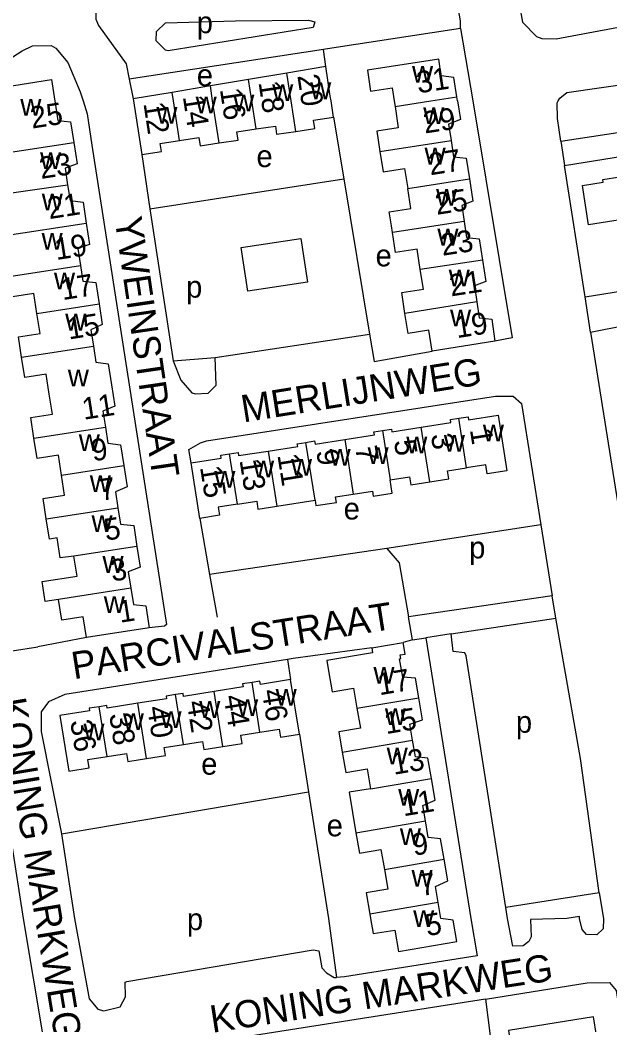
# Model space of a CAD drawing. Extents: x 159675 to 162108, y 386471 to 388472.
# Drawn here: x 160527.6 to 160635.8, y 387080.5 to 387264.8 of the extents above; entities that cross this region are included whole.
import ezdxf

# ---------------------------------------------------------------- set-up
doc = ezdxf.new("R2010")
doc.units = 0
for name, color, linetype in [('BLT_Basislijn', 7, 'Continuous'), ('BLT_Bebouwing', 7, 'Continuous'), ('BLT_Centroide', 7, 'Continuous'), ('BLT_Huisnummer', 7, 'Continuous'), ('BLT_Huisnummer_ tussenligend', 7, 'Continuous'), ('BLT_Onderverdeling_panden', 7, 'Continuous'), ('BLT_Straatnaam', 7, 'Continuous')]:
    doc.layers.add(name, color=color, linetype=linetype)

msp = doc.modelspace()

# ---------------------------------------------------------------- linework, layer by layer
at = {"layer": 'BLT_Basislijn'}
for p, q in [((160608.39, 387263.31), (160610.61, 387250)), ((160583.24, 387259.43), (160547.57, 387254.03)), ((160583.66, 387256.31), (160583.24, 387259.43)), ((160547.57, 387254.03), (160548.32, 387250.37)), ((160585.06, 387247.02), (160586.93, 387235.71)), ((160627.45, 387238.19), (160689.22, 387248.08)), ((160626.76, 387242.65), (160627.45, 387238.19)), ((160549.87, 387240.15), (160551.38, 387230.21)), ((160551.38, 387230.21), (160586.93, 387235.71)), ((160586.93, 387235.71), (160591.67, 387207.2)), ((160551.38, 387230.21), (160555.63, 387202.32)), ((160631.23, 387214.07), (160671.48, 387220.54)), ((160632.21, 387207.58), (160631.23, 387214.07)), ((160632.21, 387207.58), (160639.03, 387208.93)), ((160563.34, 387202.93), (160591.67, 387207.2)), ((160555.63, 387202.32), (160563.34, 387202.93)), ((160560.54, 387173.4), (160562.32, 387163.13)), ((160623.13, 387172.21), (160594.84, 387167.88)), ((160623.13, 387172.21), (160625.17, 387159.18)), ((160594.84, 387167.88), (160562.32, 387163.13)), ((160562.32, 387163.13), (160563.69, 387155.25)), ((160625.17, 387159.18), (160598.8, 387155.31)), ((160625.83, 387155.07), (160625.17, 387159.18)), ((160599.55, 387151.11), (160598.8, 387155.31)), ((160606.67, 387152.23), (160625.83, 387155.07)), ((160630.38, 387129.33), (160625.83, 387155.07)), ((160539.73, 387151.54), (160530.8, 387149.82)), ((160599.55, 387151.11), (160597.84, 387150.61)), ((160599.55, 387151.11), (160602.02, 387151.49)), ((160606.67, 387152.23), (160602.02, 387151.49)), ((160526.11, 387149.08), (160530.8, 387149.82)), ((160576.6, 387147.54), (160577.19, 387143.83)), ((160578.8, 387133.78), (160580.48, 387123.24)), ((160633.79, 387104.72), (160630.38, 387129.33)), ((160535.15, 387115.53), (160580.48, 387123.24)), ((160633.79, 387104.72), (160616.66, 387102))]:
    msp.add_line(p, q, dxfattribs=at)
for points in [[(160608.39, 387263.31), (160608.39, 387264.71), (160606.91, 387273.02), (160605.41, 387274.93), (160594.73, 387274.96), (160594.31, 387274.52), (160594.06, 387269.42), (160593.75, 387269.01), (160557.12, 387269.57), (160556.66, 387273.85), (160555.19, 387274.98), (160545.49, 387273.39), (160543.1, 387271.61), (160541.45, 387268.66), (160541.45, 387265), (160541.92, 387263.87), (160547, 387256.8), (160547.57, 387254.03)], [(160618.08, 387273.69), (160619.73, 387264.46), (160622.28, 387261.82), (160623.3, 387261.46), (160625.94, 387261.42), (160643.22, 387264.62), (160645.03, 387266.59)], [(160567.06, 387264.7), (160580.48, 387264.84), (160581.65, 387264.55), (160581.32, 387263.47), (160554.72, 387259.2), (160554.24, 387259.3), (160552.53, 387261.02), (160552.58, 387262.77), (160554.27, 387264.36), (160567.06, 387264.7)], [(160608.39, 387263.31), (160583.95, 387259.54), (160583.24, 387259.43)], [(160513.63, 387250), (160527.93, 387259.23), (160529.83, 387260.15), (160533.25, 387260.2), (160534.14, 387259.72), (160536.35, 387257.05), (160538.58, 387251.67), (160539.11, 387250)], [(160626.28, 387250), (160626.58, 387250.54), (160627.89, 387251.53), (160647.35, 387254.35)], [(160539.11, 387250), (160539.86, 387247.66), (160540.75, 387241.89)], [(160610.61, 387250), (160617.86, 387206.53), (160614.67, 387205.95)], [(160626.76, 387242.65), (160626.13, 387246.76), (160626.1, 387249.66), (160626.28, 387250)], [(160626.76, 387242.65), (160655.7, 387247.02), (160655.92, 387247.72), (160652.97, 387250)], [(160540.75, 387241.89), (160554.4, 387153.93), (160554.08, 387153.61), (160551.26, 387153.35)], [(160631.23, 387214.07), (160631.17, 387214.43), (160627.45, 387238.19)], [(160591.67, 387207.2), (160592.5, 387202.18), (160603.14, 387204.11)], [(160632.21, 387207.58), (160649.34, 387100), (160649.87, 387098.07)], [(160555.63, 387202.32), (160557.07, 387198.77), (160559.05, 387196.47), (160559.68, 387196.26), (160562.05, 387196.38), (160563.56, 387197.85), (160563.34, 387202.93)], [(160558.92, 387183.59), (160558.52, 387186.03), (160560.69, 387187.29), (160561.76, 387187.66), (160614.79, 387195.84), (160618.03, 387195.84), (160619.58, 387194.51), (160623.13, 387172.21)], [(160594.84, 387167.88), (160597.14, 387165.23), (160598.8, 387155.31)], [(160602.02, 387151.49), (160610.25, 387100), (160611.42, 387093.14), (160587.1, 387089.27), (160585.62, 387089.18)], [(160616.66, 387102), (160609.39, 387148.21), (160609.18, 387148.71), (160607.04, 387148.97), (160606.67, 387152.23)], [(160592.07, 387149.63), (160577.65, 387147.7), (160576.6, 387147.54)], [(160576.6, 387147.54), (160535.78, 387141.1), (160532.76, 387139.74), (160531.45, 387137.88), (160531.42, 387134.27), (160535.15, 387115.53)], [(160580.48, 387123.24), (160584.17, 387100), (160585.62, 387089.18)], [(160525.82, 387114.65), (160525.96, 387113.82), (160528.15, 387100), (160531.84, 387077.71)], [(160535.15, 387115.53), (160537.56, 387100), (160540.24, 387085.27), (160541.84, 387083.36), (160542.95, 387083.03), (160545.92, 387083.78), (160546.88, 387085.59), (160546.82, 387088.32), (160547.17, 387088.44), (160581.36, 387094.22), (160582.38, 387094.03), (160582.92, 387090.91), (160583.78, 387090.02), (160585.21, 387089.16), (160585.62, 387089.18)], [(160633.79, 387104.72), (160634.59, 387100), (160634.55, 387098.11), (160633.4, 387096.96), (160631.48, 387097.04), (160630.69, 387097.98), (160630.21, 387100), (160630.17, 387100.37), (160627.87, 387100), (160621.18, 387099.79), (160621.35, 387096.6), (160620.87, 387095.76), (160619.86, 387094.95), (160617.98, 387094.89), (160616.96, 387100), (160616.66, 387102)], [(160612.92, 387085.16), (160631.58, 387088.2), (160635.7, 387088.25), (160636.9, 387086.77), (160641.18, 387058.71)], [(160612.92, 387085.16), (160539.47, 387073.63), (160538.99, 387073.76), (160537.63, 387074.35)], [(160612.92, 387085.16), (160613.78, 387078.48), (160616.69, 387061.42)]]:
    msp.add_lwpolyline(points, dxfattribs=at)
msp.add_lwpolyline([(160568.1, 387223.09), (160579.06, 387224.78), (160580.3, 387216.78), (160569.34, 387215.09)], close=True, dxfattribs=at)
at = {"layer": 'BLT_Bebouwing'}
for p, q in [((160583.66, 387256.31), (160576.52, 387255.11)), ((160576.52, 387255.11), (160569.49, 387253.93)), ((160562.48, 387252.75), (160555.46, 387251.57)), ((160569.49, 387253.93), (160562.48, 387252.75)), ((160555.46, 387251.57), (160548.32, 387250.37)), ((160548.32, 387250.37), (160548.38, 387250)), ((160607.83, 387250), (160607.71, 387250.74)), ((160548.38, 387250), (160549.87, 387240.15)), ((160585.06, 387247.02), (160584.62, 387250)), ((160596.19, 387250), (160596.35, 387248.98)), ((160614.67, 387205.95), (160603.14, 387204.11)), ((160560.54, 387173.4), (160558.92, 387183.59)), ((160574.65, 387175.64), (160581.67, 387176.75)), ((160551.26, 387153.35), (160539.73, 387151.54)), ((160592.07, 387149.63), (160597.84, 387150.61)), ((160578.8, 387133.78), (160577.19, 387143.83))]:
    msp.add_line(p, q, dxfattribs=at)
for points in [[(160584.62, 387250), (160584.48, 387250.9), (160583.66, 387256.31)], [(160607.71, 387250.74), (160607.17, 387254.33), (160604.83, 387254.59), (160604.36, 387257.68), (160591.27, 387255.68), (160591.86, 387251.82), (160595.81, 387252.43), (160596.19, 387250)], [(160521.8, 387239.99), (160520.14, 387250.6), (160522.32, 387250.94), (160522.13, 387252.19), (160533.3, 387253.94)], [(160533.3, 387253.94), (160534.48, 387246.4), (160536.81, 387246.19), (160537.41, 387242.37)], [(160596.35, 387248.98), (160596.95, 387245.08), (160593, 387244.47), (160593.58, 387240.73)], [(160607.83, 387250), (160608.35, 387246.59), (160606.19, 387245.75), (160606.65, 387242.76)], [(160578.13, 387244.43), (160581.63, 387244.96), (160581.41, 387246.46), (160585.06, 387247.02)], [(160564.06, 387242.3), (160567.55, 387242.83), (160567.32, 387244.33), (160570.86, 387244.86)], [(160570.86, 387244.86), (160574.4, 387245.4), (160574.63, 387243.9), (160578.13, 387244.43)], [(160556.8, 387242.74), (160560.34, 387243.27), (160560.57, 387241.77), (160564.06, 387242.3)], [(160537.41, 387242.37), (160538.02, 387238.47), (160535.82, 387237.67), (160536.29, 387234.62)], [(160549.87, 387240.15), (160553.49, 387240.7), (160553.26, 387242.2), (160556.8, 387242.74)], [(160606.65, 387242.76), (160607.1, 387239.77), (160609.42, 387239.51), (160610.01, 387235.69)], [(160593.58, 387240.73), (160594.16, 387237), (160598.11, 387237.61), (160598.68, 387233.93)], [(160610.01, 387235.69), (160610.62, 387231.64), (160608.58, 387230.85), (160609.03, 387227.9)], [(160641.94, 387228.84), (160631.85, 387227.28), (160630.74, 387234.49), (160634.56, 387235.09), (160634.48, 387235.61), (160640.74, 387236.58)], [(160536.29, 387234.62), (160536.74, 387231.75), (160539.11, 387231.45), (160539.71, 387227.57)], [(160595.88, 387225.89), (160595.69, 387227.11), (160595.3, 387229.64), (160599.25, 387230.26), (160598.68, 387233.93)], [(160539.71, 387227.57), (160540.32, 387223.67), (160538.16, 387222.91), (160538.64, 387219.82)], [(160609.03, 387227.9), (160609.48, 387224.95), (160611.79, 387224.7), (160612.39, 387220.8)], [(160600.99, 387219.06), (160600.41, 387222.79), (160596.45, 387222.17), (160595.88, 387225.89)], [(160538.64, 387219.82), (160539.09, 387216.96), (160541.43, 387216.68), (160542.04, 387212.75)], [(160598.18, 387211.02), (160597.59, 387214.83), (160601.55, 387215.44), (160600.99, 387219.06)], [(160612.39, 387220.8), (160612.98, 387216.9), (160610.92, 387216.05), (160611.37, 387213.13)], [(160530.66, 387211.01), (160530.1, 387214.69), (160526.15, 387214.09), (160525.58, 387217.82)], [(160542.04, 387212.75), (160542.63, 387208.98), (160540.53, 387208.01), (160541, 387205)], [(160611.37, 387213.13), (160611.81, 387210.21), (160614.14, 387209.94), (160614.67, 387205.95)], [(160527.84, 387202.99), (160527.27, 387206.73), (160531.22, 387207.34), (160530.66, 387211.01)], [(160603.14, 387204.11), (160602.53, 387207.93), (160598.75, 387207.34), (160598.18, 387211.02)], [(160541, 387205), (160541.45, 387202.1), (160543.73, 387201.75), (160544.33, 387197.92)], [(160532.92, 387196.17), (160532.36, 387199.85), (160528.41, 387199.25), (160527.84, 387202.99)], [(160544.33, 387197.92), (160544.94, 387194), (160542.77, 387193.1), (160543.23, 387190.15)], [(160530.1, 387188.15), (160529.53, 387191.89), (160533.48, 387192.5), (160532.92, 387196.17)], [(160601.14, 387190.13), (160606.6, 387190.99), (160606.51, 387191.54), (160608.05, 387191.78)], [(160608.05, 387191.78), (160609.74, 387192.04), (160609.83, 387191.47), (160615.28, 387192.32), (160616.87, 387182.13), (160613.28, 387181.57), (160613.02, 387183.25), (160609.49, 387182.69)], [(160543.23, 387190.15), (160543.69, 387187.19), (160546.01, 387186.89), (160546.61, 387183.08)], [(160587.12, 387187.86), (160592.57, 387188.71), (160592.48, 387189.28), (160594.08, 387189.53)], [(160594.08, 387189.53), (160595.69, 387189.78), (160595.77, 387189.29), (160601.14, 387190.13)], [(160535.18, 387181.34), (160534.62, 387185.01), (160530.67, 387184.41), (160530.1, 387188.15)], [(160580.01, 387187.36), (160581.58, 387187.61), (160581.67, 387187.01), (160587.12, 387187.86)], [(160573.06, 387185.77), (160578.49, 387186.62), (160578.41, 387187.11), (160580.01, 387187.36)], [(160558.92, 387183.59), (160564.46, 387184.46), (160564.37, 387184.99), (160565.98, 387185.24)], [(160565.98, 387185.24), (160567.55, 387185.49), (160567.64, 387184.92), (160573.06, 387185.77)], [(160546.61, 387183.08), (160547.21, 387179.2), (160545.04, 387178.3), (160545.5, 387175.33)], [(160602.73, 387180.09), (160606.21, 387180.64), (160605.97, 387182.14), (160609.49, 387182.69)], [(160532.36, 387173.33), (160531.79, 387177.07), (160535.74, 387177.67), (160535.18, 387181.34)], [(160588.68, 387177.86), (160592.21, 387178.42), (160592.35, 387177.51), (160595.81, 387178.06), (160595.44, 387180.46)], [(160595.44, 387180.46), (160599.02, 387181.03), (160599.26, 387179.54), (160602.73, 387180.09)], [(160567.44, 387176.03), (160570.97, 387176.59), (160571.21, 387175.09), (160574.65, 387175.64)], [(160581.67, 387176.75), (160581.83, 387175.75), (160585.59, 387176.33), (160585.43, 387177.35), (160588.68, 387177.86)], [(160545.5, 387175.33), (160545.97, 387172.35), (160548.4, 387172.1), (160549, 387168.27)], [(160567.44, 387176.03), (160563.92, 387175.47), (160564.15, 387173.98), (160560.54, 387173.4)], [(160537.45, 387166.46), (160534.92, 387166.15), (160534.36, 387169.81), (160532.93, 387169.59), (160532.36, 387173.33)], [(160549, 387168.27), (160549.6, 387164.44), (160547.4, 387163.57), (160547.87, 387160.59)], [(160534.62, 387158.52), (160532.18, 387158.13), (160531.61, 387161.84), (160538.01, 387162.82), (160537.45, 387166.46)], [(160547.87, 387160.59), (160548.34, 387157.61), (160550.63, 387157.38), (160551.26, 387153.35)], [(160539.73, 387151.54), (160539.13, 387155.35), (160535.19, 387154.75), (160534.62, 387158.52)], [(160592.07, 387149.63), (160592.22, 387148.73), (160583.82, 387147.3), (160584.14, 387145.43), (160584.8, 387141.57), (160588.74, 387142.24), (160589.36, 387138.57)], [(160600.69, 387140.5), (160600.08, 387144.1), (160597.78, 387144.26), (160597.2, 387147.64), (160597.41, 387147.68), (160597.3, 387148.34), (160598.2, 387148.49), (160597.84, 387150.61)], [(160577.19, 387143.83), (160571.64, 387142.94), (160571.54, 387143.55), (160570.11, 387143.32)], [(160563.17, 387141.64), (160557.55, 387140.74), (160557.46, 387141.28), (160556.06, 387141.06)], [(160570.11, 387143.32), (160568.39, 387143.05), (160568.48, 387142.49), (160563.17, 387141.64)], [(160556.06, 387141.06), (160554.35, 387140.79), (160554.42, 387140.32), (160549.15, 387139.47)], [(160599.56, 387132.7), (160599.06, 387135.64), (160601.38, 387136.46), (160600.69, 387140.5)], [(160542.08, 387138.84), (160540.23, 387138.55), (160540.31, 387138.09), (160534.86, 387137.22), (160536.49, 387127.04), (160540.25, 387127.64), (160540.01, 387129.14), (160543.53, 387129.7)], [(160549.15, 387139.47), (160543.53, 387138.58), (160543.45, 387139.07), (160542.08, 387138.84)], [(160589.36, 387138.57), (160589.99, 387134.91), (160586.04, 387134.24), (160586.68, 387130.51)], [(160564.78, 387131.55), (160568.28, 387132.11), (160568.04, 387133.61), (160571.57, 387134.17)], [(160571.57, 387134.17), (160575.09, 387134.73), (160575.33, 387133.23), (160578.8, 387133.78)], [(160557.52, 387131.93), (160561.05, 387132.49), (160561.29, 387130.99), (160564.78, 387131.55)], [(160603.02, 387125.68), (160602.39, 387129.41), (160600.08, 387129.65), (160599.56, 387132.7)], [(160550.76, 387129.32), (160554.23, 387129.88), (160553.99, 387131.37), (160557.52, 387131.93)], [(160586.68, 387130.51), (160587.31, 387126.78), (160591.25, 387127.46), (160591.88, 387123.79)], [(160543.53, 387129.7), (160547.06, 387130.26), (160547.3, 387128.77), (160550.76, 387129.32)], [(160601.92, 387117.89), (160601.45, 387120.71), (160603.7, 387121.68), (160603.02, 387125.68)], [(160591.88, 387123.79), (160587.92, 387123.18), (160588.56, 387119.45), (160589.19, 387115.72)], [(160605.34, 387110.87), (160604.71, 387114.58), (160602.43, 387114.87), (160601.92, 387117.89)], [(160589.19, 387115.72), (160589.83, 387111.99), (160593.77, 387112.67), (160594.39, 387109)], [(160604.29, 387102.92), (160603.79, 387105.88), (160606.01, 387106.88), (160605.34, 387110.87)], [(160594.39, 387109), (160595.02, 387105.34), (160591.07, 387104.67), (160591.73, 387100.8)], [(160591.73, 387100.8), (160591.87, 387100), (160592.34, 387097.2), (160596.29, 387097.87), (160596.96, 387093.93), (160607.68, 387095.75), (160607.01, 387099.7), (160604.78, 387100), (160604.29, 387102.92)], [(160632.76, 387081.95), (160617.16, 387079.46), (160617.79, 387075.55), (160616.9, 387075.41), (160617.04, 387074.56), (160617.9, 387074.69), (160618.7, 387069.68), (160617.3, 387069.46), (160618.68, 387060.87), (160627.39, 387062.26), (160627.19, 387063.5), (160635.49, 387064.83), (160632.76, 387081.95)]]:
    msp.add_lwpolyline(points, dxfattribs=at)
at = {"layer": 'BLT_Onderverdeling_panden'}
for p, q in [((160577.29, 387250), (160576.52, 387255.11)), ((160562.89, 387250), (160562.48, 387252.75)), ((160570.09, 387250), (160569.49, 387253.93)), ((160555.7, 387250), (160555.46, 387251.57)), ((160602.93, 387250), (160607.71, 387250.74)), ((160556.8, 387242.74), (160555.7, 387250)), ((160564.06, 387242.3), (160562.89, 387250)), ((160570.86, 387244.86), (160570.09, 387250)), ((160578.13, 387244.43), (160577.29, 387250)), ((160596.35, 387248.98), (160602.93, 387250)), ((160521.8, 387239.99), (160537.41, 387242.37)), ((160593.58, 387240.73), (160606.65, 387242.76)), ((160598.68, 387233.93), (160610.01, 387235.69)), ((160518.72, 387232.15), (160536.29, 387234.62)), ((160524.45, 387225.23), (160539.71, 387227.57)), ((160609.03, 387227.9), (160595.88, 387225.89)), ((160525.58, 387217.82), (160538.64, 387219.82)), ((160612.39, 387220.8), (160600.99, 387219.06)), ((160530.66, 387211.01), (160542.04, 387212.75)), ((160611.37, 387213.13), (160598.18, 387211.02)), ((160527.84, 387202.99), (160541, 387205)), ((160609.49, 387182.69), (160608.05, 387191.78)), ((160530.1, 387188.15), (160543.23, 387190.15)), ((160594.08, 387189.53), (160595.44, 387180.46)), ((160602.73, 387180.09), (160601.14, 387190.13)), ((160587.12, 387187.86), (160588.68, 387177.86)), ((160581.67, 387176.75), (160580.01, 387187.36)), ((160567.44, 387176.03), (160565.98, 387185.24)), ((160573.06, 387185.77), (160574.65, 387175.64)), ((160535.18, 387181.34), (160546.61, 387183.08)), ((160532.36, 387173.33), (160545.5, 387175.33)), ((160549, 387168.27), (160537.45, 387166.46)), ((160547.87, 387160.59), (160534.62, 387158.52)), ((160564.78, 387131.55), (160563.17, 387141.64)), ((160571.57, 387134.17), (160570.11, 387143.32)), ((160557.52, 387131.93), (160556.06, 387141.06)), ((160589.36, 387138.57), (160600.69, 387140.5)), ((160543.53, 387129.7), (160542.08, 387138.84)), ((160550.76, 387129.32), (160549.15, 387139.47)), ((160586.68, 387130.51), (160599.56, 387132.7)), ((160591.88, 387123.79), (160603.02, 387125.68)), ((160589.19, 387115.72), (160601.92, 387117.89)), ((160594.39, 387109), (160605.34, 387110.87)), ((160604.29, 387102.92), (160591.73, 387100.8))]:
    msp.add_line(p, q, dxfattribs=at)

# ---------------------------------------------------------------- texts
at = {"layer": 'BLT_Centroide'}
for s, p in [('p', (160559.96, 387262.43)), ('e', (160559.99, 387252.74)), ('w', (160599.47, 387253.34)), ('w', (160573.81, 387249.98)), ('w', (160580.78, 387250.33)), ('w', (160527.6, 387247.28)), ('w', (160559.77, 387247.73)), ('w', (160566.67, 387248.08)), ('w', (160552.56, 387245.83)), ('w', (160601.52, 387245.75)), ('w', (160601.77, 387238.34)), ('w', (160531.23, 387237.5)), ('e', (160570.93, 387237.87)), ('w', (160603.88, 387230.78)), ('w', (160531.54, 387229.94)), ('w', (160604.12, 387223.47)), ('w', (160531.51, 387222.69)), ('e', (160592.78, 387219.65)), ('w', (160606.2, 387215.97)), ('w', (160533.78, 387215.41)), ('p', (160558.02, 387213.91)), ('w', (160606.45, 387208.62)), ('w', (160535.84, 387207.88)), ('w', (160536.32, 387197.62)), ('w', (160612.47, 387187.52)), ('w', (160538.33, 387185.75)), ('w', (160598.41, 387185.33)), ('w', (160605.31, 387185.64)), ('w', (160584.34, 387183.08)), ('w', (160591.31, 387183.39)), ('w', (160570.31, 387180.91)), ('w', (160577.27, 387181.25)), ('w', (160563.19, 387179.03)), ('w', (160540.35, 387178.22)), ('e', (160586.93, 387173.2)), ('w', (160540.66, 387170.91)), ('p', (160609.95, 387166.06)), ('w', (160542.68, 387163.41)), ('w', (160542.91, 387156.06)), ('w', (160592.39, 387143.09)), ('w', (160574.45, 387139.02)), ('w', (160560.42, 387136.8)), ('w', (160567.38, 387137.14)), ('w', (160553.33, 387134.94)), ('w', (160594.48, 387135.5)), ('w', (160546.42, 387134.59)), ('p', (160618.53, 387134.06)), ('w', (160539.19, 387132.69)), ('w', (160594.82, 387128.25)), ('e', (160560.79, 387126.37)), ('w', (160596.93, 387120.69)), ('e', (160583.81, 387115.06)), ('w', (160597.24, 387113.44)), ('w', (160599.37, 387105.84)), ('p', (160558.17, 387097.85)), ('w', (160599.68, 387098.44))]:
    msp.add_text(s, height=4, dxfattribs=at).set_placement(p)
at = {"layer": 'BLT_Huisnummer'}
for s, rotation, p in [('31', 8.8144, (160600.6, 387251.38)), ('20', 278.6115, (160578.42, 387254.66)), ('16', 278.6115, (160564.21, 387252.14)), ('25', 8.8887, (160529.75, 387244.92)), ('12', 278.6115, (160550.18, 387249.56)), ('27', 8.8144, (160602.82, 387236.36)), ('21', 8.8887, (160532.92, 387228.31)), ('23', 8.8144, (160605.06, 387221.58)), ('17', 8.8887, (160535.37, 387213.45)), ('15', 8.8829, (160536.5, 387206.22)), ('19', 8.8144, (160607.71, 387206.47)), ('11', 8.8829, (160539.24, 387191.49)), ('1', 279.0076, (160610.07, 387189.69)), ('9', 8.8887, (160540.93, 387183.86)), ('5', 279.0076, (160596.13, 387187.61)), ('9', 279.0076, (160581.88, 387185.8)), ('15', 279.0076, (160560.56, 387182.81)), ('5', 8.8887, (160543.29, 387169.31)), ('1', 8.8887, (160545.9, 387154.24)), ('17', 9.6148, (160593.49, 387140.93)), ('46', 279.0997, (160571.89, 387141.79)), ('40', 279.0997, (160550.85, 387138.71)), ('36', 279.0997, (160536.74, 387136.2)), ('13', 9.6148, (160596.12, 387126.34)), ('9', 9.6148, (160599.79, 387111.48)), ('5', 9.6148, (160602.24, 387096.73))]:
    msp.add_text(s, height=4, rotation=rotation, dxfattribs=at).set_placement(p)
at = {"layer": 'BLT_Huisnummer_ tussenligend'}
for s, rotation, p in [('18', 278.6097, (160571.29, 387253.43)), ('14', 278.6097, (160557.41, 387250.8)), ('29', 8.6933, (160601.82, 387244.02)), ('23', 8.8829, (160531.4, 387235.68)), ('25', 8.6933, (160604.01, 387229.1)), ('19', 8.8829, (160534.2, 387220.8)), ('21', 8.6933, (160606.63, 387214.13)), ('3', 279.0037, (160602.91, 387188.73)), ('7', 279.0037, (160589.03, 387186.45)), ('13', 279.0037, (160567.81, 387184.09)), ('11', 279.0037, (160574.76, 387185.02)), ('7', 8.8829, (160542.4, 387176.61)), ('3', 8.8829, (160544.47, 387161.8)), ('42', 279.0534, (160558.12, 387139.72)), ('44', 279.0534, (160564.88, 387140.77)), ('15', 9.6124, (160594.71, 387133.8)), ('38', 279.0534, (160543.89, 387137.43)), ('11', 9.6124, (160597.9, 387118.72)), ('7', 9.6124, (160601.17, 387104.08))]:
    msp.add_text(s, height=4, rotation=rotation, dxfattribs=at).set_placement(p)
at = {"layer": 'BLT_Straatnaam'}
for s, height, rotation, p in [('YWEINSTRAAT', 5, 278.3275, (160544.88, 387228.41)), ('MERLIJNWEG', 5, 9.0624, (160568.52, 387191)), ('PARCIVALSTRAAT', 5, 8.968, (160537.41, 387143.87)), ('KONING MARKWEG', 4.9999, 279.4042, (160523.63, 387140.08)), ('KONING MARKWEG', 5, 8.7398, (160562.81, 387078.99))]:
    msp.add_text(s, height=height, rotation=rotation, dxfattribs=at).set_placement(p)

doc.saveas('drawing.dxf')
